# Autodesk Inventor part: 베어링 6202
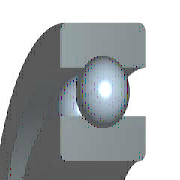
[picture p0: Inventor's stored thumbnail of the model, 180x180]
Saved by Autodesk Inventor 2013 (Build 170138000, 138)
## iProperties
IsCustomPart: 1
Created: 2015-12
Part Number: 베어링 6202
Material: 강철, 연강
Description: 깊은 그루브 볼 베어링
Document SubType Name: Modeling
Standard: KS B 2023
Designer: mdu
Standards Organization: KS
Language: ko-KR
Size Designation: 6202 - 15 x 35 x 11
Categories: <MemberInstance><Categories><Category DisplayName="샤프트 부품" InternalName="7f7aeb1f-a693-4053-b835-cee3144e0d98" Mnemonic="SHFT"><Category DisplayName="베어링" Inter
Density: 7.86 g/cm^3
Mass: 45.8725 g
Surface Area: 51.5584 cm^2
Volume: 5.83619 cm^3
Author: mdu
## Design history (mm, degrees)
sketch "스케치" dims "d0" = 5.2 (= -0.26 x WD + 0.26 x BD)
  geometry: L1 (2.9, 12.5)-(8.1, 12.5); L2 (5.5, 12.5)-(5.5, 9.9); L3 (5.5, 12.5)-(5.5, 15.1); L4 (3.568, 10.76)-(0, 10.76); L5 (0, 7.5)-(11, 7.5); L6 (3.568, 14.24)-(0, 14.24); L7 (0, 17.5)-(11, 17.5); L8 (11, 7.5)-(11, 10.76); L9 (7.432, 10.76)-(11, 10.76); L10 (7.432, 14.24)-(11, 14.24); L11 (11, 17.5)-(11, 14.24); L12 (-1.4, 0)-(8.4, 0) reference; L13 (0, -0.3)-(0, 5.3) reference
  constraints: 22 end point, 4 point on line, 2 collinear, 2 perpendicular, 2 symmetric about line, 1 midpoint, 1 parallel, 14 other
  dimensions: "d9" = 15 diameter of L5 L12 (= WD); "d11" = 35 diameter of L7 L12 (= BD); "d12" = 11 distance between parallel lines of L8 L13 (= KB); "d13" = 21.52 diameter of L9 L12 (= 0.326 x BD + 0.674 x WD)
revolve "본체" stored, may be unused: angle "d6" = 90 deg
revolve "볼" stored, may be unused: angle "d7" = 90 deg
pattern_circular "IDS_ARRAYBALL[SIMPL:T]" dims angle "d3" = 360 deg
body "Solid1"
fillet "모깎기1" dims "d1" = 0.6 (= KRS)
other parameters: "WD" = 15 [user parameter; used in 5 equation terms], "BD" = 35 [user parameter; used in 5 equation terms], "KB" = 11 [user parameter; used in 1 equation term], "KRS" = 0.6 [user parameter; used in 1 equation term], "d4" = 0, "d5" = 0, "d8" = 0, "d14" = 0, "d15" = 0, "BBA" = 0 [user parameter], "BC0" = 3750000 [user parameter], "BC" = 7800000 [user parameter], "BR" = 17.5 (= 0.5 x BD) [user parameter], "WR" = 7.5 (= 0.5 x WD) [user parameter]
